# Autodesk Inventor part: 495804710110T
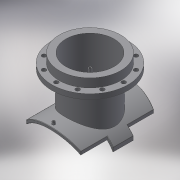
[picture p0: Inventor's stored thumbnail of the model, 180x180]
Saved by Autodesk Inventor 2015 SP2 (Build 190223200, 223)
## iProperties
Created: 2017-10
Part Number: 495804710110T
Material: Generic
Description: PLASSON FLANGED BRANCH SADDLE 450-800X150
Document SubType Name: Modeling
Designer: KIM
Density: 1 g/cm^3
Appearance: Default
Author: KIM
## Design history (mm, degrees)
derived "495904.ipt"
feature "Solid1::495904.ipt"
feature "Solid2::495904.ipt"
tag "TaggingFeature1"
body "Solid1"
other parameters: "d1" = 15, "d2" = 283.5, "d4" = 0, "d5" = 315, "d6" = 75, "d7" = 0, "d11" = 4, "d12" = 425.6, "d13" = 14, "d14" = 135, "d16" = 5 deg, "d18" = 4, "d19" = 14, "d20" = 0, "d21" = 3, "d22" = 0, "d23" = 536, "d36" = 135, "d38" = 0, "d39" = 2, "d40" = 121, "d42" = 212, "d43" = 285, "d44" = 96.8, "d46" = 169.6, "d47" = 16, "d48" = 10.4, "d49" = 84.7, "d51" = 816, "d53" = 0, "d54" = 18, "d57" = 0, "d59" = 360 deg, "d61" = 24, "d63" = 0, "d_1" = 212, "B_" = 315, "H_" = 121, "x_" = 15, "D_" = 16, "D_1" = 285, "t_" = 24, "s_" = 18
